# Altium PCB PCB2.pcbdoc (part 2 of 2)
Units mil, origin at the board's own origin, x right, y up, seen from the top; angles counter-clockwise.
Board outline 3822.51 x 2229.86 mil, 2 copper layers (Top Layer, Bottom Layer); 117 components, 92 nets, 474 pads, 260 vias.
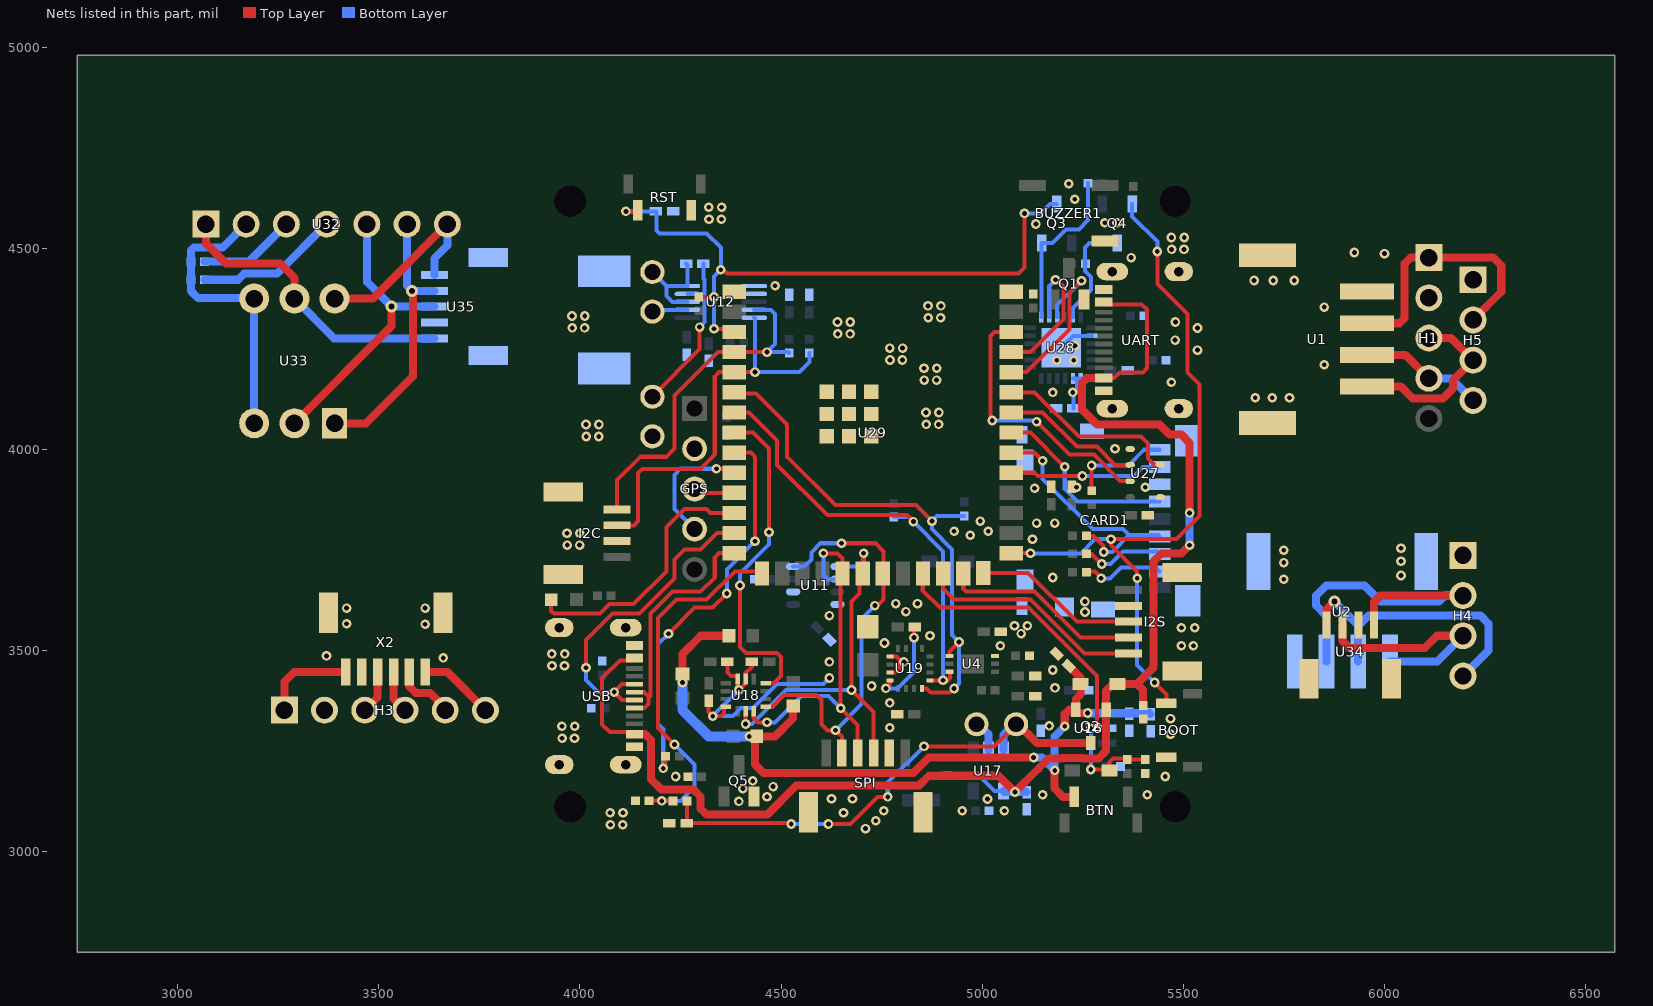
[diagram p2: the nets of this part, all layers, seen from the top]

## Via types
v1: diameter 24.02, hole 12.01, Top Layer to Bottom Layer, 252 vias
v2: diameter 24, hole 12, Top Layer to Bottom Layer, 5 vias
v3: diameter 30, hole 15, Top Layer to Bottom Layer, 3 vias

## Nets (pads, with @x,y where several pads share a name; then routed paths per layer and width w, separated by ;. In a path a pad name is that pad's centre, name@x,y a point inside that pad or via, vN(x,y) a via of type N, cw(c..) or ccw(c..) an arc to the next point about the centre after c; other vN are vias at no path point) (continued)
DATA0: CARD1.7 U29.31 | length 381.6
  Top Layer w10: U29.31@5072.19,3941.69 5130.22,3941.69 5138.34,3933.57 v1(5248.89,3933.57)
  Bottom Layer w10: v1(5248.89,3933.57) 5377.09,3933.57 5400.02,3956.5 5440.75,3956.5 CARD1.7@5440.85,3956.4
DATA1: CARD1.8 R61.2 | length 248.1
  Top Layer w10: R61.2@5271.88,3896.94 v1(5271.88,3959.9)
  Bottom Layer w10: v1(5271.88,3959.9) 5363.42,3959.9 5402.42,3998.9 CARD1.8@5440.85,3998.9
DATA2: CARD1.1 R58.2 | length 211.3
  Top Layer w10: R58.2@5258.92,3689.9 5258.92,3695.4 5260.02,3696.5 5280.02,3696.5 5295.47,3681.05 v1(5295.47,3679.39)
  Bottom Layer w10: v1(5295.47,3679.39) 5317.91,3679.39 5345.02,3706.5 5430.85,3706.5 CARD1.1@5440.85,3696.5
DATA3: CARD1.2 R59.2 | length 208.1
  Top Layer w10: R59.2@5258.92,3739.9 5271.88,3739.9 v1(5296.88,3714.9)
  Bottom Layer w10: v1(5296.88,3714.9) 5318.42,3714.9 5350.02,3746.5 5434.15,3746.5 CARD1.2@5440.85,3739.8
DTR: Q4.3 R62.1 U28.23 | length 283.7
  Bottom Layer w10: U28.23@5225.56,4329.27 5225.02,4329.81 5225.02,4351.5 5270.02,4396.5 5270.02,4428.08 5255.02,4443.08 5255.02,4459.46 R62.1@5257.06,4461.5 5255.02,4463.54 5255.02,4501.5 5266.4,4512.87 Q4.3@5335.02,4512.87
E12S_GAIN: R75.2 U32.4 | length 360.3
  Bottom Layer w20: R75.2@3067.06,4421.5 3150.02,4421.5 3165.02,4436.5 3247.02,4436.5 U32.4@3370.18,4559.66
E12S_SD: R76.2 U32.3 | length 241.7
  Bottom Layer w20: R76.2@3067.06,4466.5 3177.02,4466.5 U32.3@3270.18,4559.66
EI2S_3.3V: U32.1 U33.5 U35.5 | length 744.2
  Top Layer w20: U32.1@3070.18,4559.66 3070.18,4511.34 3120.02,4461.5 3255.02,4461.5 3290.18,4426.34 U33.5@3290.18,4374.66
  Bottom Layer w20: U33.5@3290.18,4374.66 3388.92,4275.91 U35.5@3638.25,4275.91
EI2S_DAT: U32.7 U33.4 U35.1 | length 496.1
  Top Layer w20: U33.4@3390.18,4374.66 3485.18,4374.66 U32.7@3670.18,4559.66
  Bottom Layer w20: U35.1@3638.25,4433.39 3638.25,4474.73 3670.18,4506.66 U32.7@3670.18,4559.66
EI2S_GND: R75.1 R76.1 U32.2 U33.3 U33.6 U35.4 U35.6 U35.7 | length 740.1
  Bottom Layer w20: U32.2@3170.18,4559.66 3112.02,4501.5 3040.02,4501.5 3032.98,4494.46 R76.1@3032.98,4466.5 R75.1@3032.98,4421.5 3032.98,4393.54 3050.02,4376.5 3188.34,4376.5 U33.6@3190.18,4374.66 U33.3@3190.18,4064.66
EI2S_SCK: U32.6 U33.1 U35.2 | length 683.4
  Top Layer w20: U33.1@3390.18,4064.66 3468.18,4064.66 3585.02,4181.5 3585.02,4391.5 v3(3582.5,4394.02)
  Bottom Layer w20: U32.6@3570.18,4559.66 3570.02,4559.5 3570.02,4406.5 v3(3582.5,4394.02) U35.2@3638.25,4394.02
EI2S_WS: U32.5 U33.2 U35.3 | length 727
  Top Layer w20: U33.2@3290.18,4064.66 3531.87,4306.34 v3(3531.87,4354.65)
  Bottom Layer w20: U32.5@3470.18,4559.66 3470.18,4416.34 v3(3531.87,4354.65) U35.3@3638.25,4354.65
ESP_D+: U29.14 USB.6 USB.8 | length 608.7
  Top Layer w10: USB.8@4135.52,3356.97 4160.43,3356.97 4169.96,3366.5 4169.96,3381.44 4175.02,3386.5 ; USB.6@4135.52,3396.34 4158.93,3396.34 4168.77,3386.5 4175.02,3386.5 ; U29.14@4383.21,3741.69 4345.22,3741.69 4335.02,3731.5 4335.02,3681.5 4300.02,3646.5 4230.02,3646.5 4175.02,3591.5 4175.02,3386.5
ESP_D-: U29.13 USB.5 USB.7 | length 805.5
  Top Layer w10: v1(4015.02,3456.79) 4015.02,3526.5 4080.31,3591.79 4147.64,3591.79 4235.02,3679.17 4235.02,3726.5 4260.02,3751.5 4300.02,3751.5 4340.22,3791.69 U29.13@4383.21,3791.69 ; USB.7@4135.52,3376.65 4104.86,3376.65 v1(4085.02,3396.5) 4104.55,3416.02 USB.5@4135.52,3416.02
  Bottom Layer w10: v1(4015.02,3456.79) 4015.02,3426.5 4045.02,3396.5 v1(4085.02,3396.5)
ESP_IO0: BOOT.1 Q4.2 U29.27 | length 1816.7
  Top Layer w10: U29.27@5072.19,3741.69 5119.82,3741.69 v1(5120.02,3741.5) ; v1(5385.02,3679.28) 5385.02,3696.5 5320.02,3761.5 v1(5320.02,3776.5) 5482.54,3776.5 5540.02,3833.98 5540.02,4161.5 5510.02,4191.5 5510.02,4336.5 5435.02,4411.5 v1(5435.02,4491.5) ; v1(5428.31,3420.21) 5457.47,3391.05 BOOT.1@5457.47,3368.5
  Bottom Layer w10: v1(5120.02,3741.5) 5245.02,3741.5 5280.02,3776.5 v1(5320.02,3776.5) ; Q4.2@5372.42,4610.12 5372.42,4579.1 5435.02,4516.5 v1(5435.02,4491.5) ; v1(5385.02,3679.28) 5385.02,3463.5 v1(5428.31,3420.21)
ESP_RST: C48.1 Q3.3 R64.2 RST.1 U29.3 | length 1621.3
  Top Layer w10: v1(4114.01,4591.5) 4140.57,4591.5 RST.1@4143.09,4594.02 ; R64.2@4295.02,4378.54 4332.79,4378.54 v1(4333.01,4378.76) ; v1(4333.01,4299.49) 4375.41,4299.49 U29.3@4383.21,4291.69 ; v1(4350.02,4446.5) 4355.02,4446.5 4365.02,4436.5 5090.02,4436.5 5105.02,4451.5 v1(5105.02,4586.5)
  Bottom Layer w10: v1(4114.01,4591.5) C48.1@4188.56,4591.5 4190.02,4590.04 4190.02,4543.57 4197.09,4536.5 4315.02,4536.5 4350.02,4501.5 v1(4350.02,4446.5) 4333.01,4429.49 v1(4333.01,4378.76) v1(4333.01,4299.49) ; v1(5105.02,4586.5) 5145.02,4586.5 5168.65,4610.12 Q3.3@5185.02,4610.12
ESP_RXD: U28.21 U29.36 | length 437.3
  Top Layer w10: U29.36@5072.19,4191.69 5110.22,4191.69 5216.4,4297.88 5216.4,4390.03 5245.18,4418.81 v2(5246.78,4418.81)
  Bottom Layer w10: U28.21@5186.19,4329.27 5186.19,4358.21 v2(5246.78,4418.81)
ESP_TXD: U28.20 U29.37 | length 370.7
  Top Layer w10: U29.37@5072.19,4241.69 5120.22,4241.69 5202.38,4323.86 5202.38,4404.14 5185.02,4421.5 v2(5182.02,4421.5)
  Bottom Layer w10: U28.20@5166.49,4329.27 5166.49,4405.97 v2(5182.02,4421.5)
ESPI_3.3V: H3.1 X2.6 | length 233.6
  Top Layer w20: H3.1@3265.02,3351.5 3265.02,3421.5 3289.76,3446.24 X2.6@3418.37,3446.24
ESPI_CS: H3.6 X2.1 | length 189
  Top Layer w20: X2.1@3615.22,3446.24 3670.28,3446.24 H3.6@3765.02,3351.5
ESPI_GND: H3.2 X2.5 X2.7 X2.8
  other v1: 3660.02,3481.5 3370.02,3486.5 3615.02,3565.27 3420.02,3566.5 3420.02,3605.27 3615.02,3605.27
ESPI_MISO: H3.5 X2.2 | length 153.2
  Top Layer w20: X2.2@3575.85,3446.24 3575.02,3445.42 3575.02,3411.43 3591.66,3394.79 3627.3,3394.79 3665.02,3357.07 H3.5@3665.02,3351.5
ESPI_MOSI: H3.4 X2.3 | length 106.6
  Top Layer w20: X2.3@3536.48,3446.24 3536.48,3380.04 H3.4@3565.02,3351.5
ESPI_SCLK: H3.3 X2.4 | length 108
  Top Layer w20: H3.3@3465.02,3351.5 3497.11,3383.58 X2.4@3497.11,3446.24
EUART_3.3V: H1.1 H5.2 U1.2 | length 652.4
  Top Layer w20: U1.2@5956.53,4313.37 6036.89,4313.37 6050.02,4326.5 6050.02,4461.5 6065.06,4476.54 H1.1@6109.98,4476.54 ; H1.1@6109.98,4476.54 6270.02,4476.5 6290.02,4456.5 6290.02,4391.58 H5.2@6219.98,4321.54
EUART_GND: H1.2 H5.1 U1.1 U1.5 U1.6
  other v1: 5678.37,4128.33 5720.65,4128.33 5763.62,4128.33 5850.24,4210.27 5850.24,4353.38 5675.77,4419.67 5723.26,4419.67 5775.3,4419.67 6000.02,4486.5 5925.04,4489.34
EUART_RXD: H1.3 H5.3 U1.4 | length 459.5
  Top Layer w20: U1.4@5956.53,4155.89 6040.63,4155.89 6070.02,4126.5 6145.02,4126.5 6170.02,4151.5 6170.02,4171.58 H5.3@6219.98,4221.54 6164.98,4276.54 H1.3@6109.98,4276.54
EUART_TXD: H1.4 H5.4 U1.3 | length 310.3
  Top Layer w20: U1.3@5956.53,4234.63 6051.89,4234.63 H1.4@6109.98,4176.54
  Bottom Layer w20: H1.4@6109.98,4176.54 6164.98,4176.54 H5.4@6219.98,4121.54
GND: BAT+.1 BOOT.2 BUZZER1.3 C1.1 C2.2 C3.1 C4.2 C5.1 C6.1 C7.2 C9.1 C14.1 C15.1 C17.1 C18.1 C19.1 C20.1 C21.1 C22.1 C32.1 C33.1 C36.1 C37.1 C42.1 C43.1 C44.2 C45.2 C46.2 C47.2 C48.2 C49.1 CARD1.6 CARD1.10 CARD1.11 CARD1.12 CARD1.13 CARD1.14 CARD1.15 CARD1.16 CARD1.17 CARD1.18 GPS.2 I2C.3 I2C.5 I2C.6 I2S.4 I2S.6 I2S.7 Q1.2 Q5.2 R1.2 R8.1 R40.1 R42.2 R43.2 R47.2 R48.2 R49.1 R54.1 R55.1 R57.2 R65.2 RST.2 SPI.5 SPI.7 SPI.8 U4.3 U11.1 U11.7 U12.1 U12.2 U12.7 U16.2 U17.2 U18.6 U18.7 U18.11 U19.9 U19.11 U27.1 U27.5 U28.2 U28.25 U29.1 U29.40 U29.41 UART.1 UART.12 UART.13 UART.14 USB.1 USB.12 USB.13 USB.14 VIN+.2 vout+.2 | length 1025.1
  Top Layer w10: C5.1@4320.02,3375.04 4320.02,3346.5 v1(4330.02,3336.5) 4350.02,3336.5 4358.07,3344.55 4358.07,3359.55 U18.11@4362.13,3359.55 ; C6.1@4366.48,3471.5 4366.48,3445.04 4375.02,3436.5 4390.02,3436.5 4392.13,3434.39 U18.7@4392.13,3428.94 4392.13,3404.39 v1(4395.02,3401.5) 4411.82,3418.3 U18.6@4411.82,3428.94 4411.82,3443.6 4427.18,3458.95 C4.2@4427.18,3472.02 ; U19.11@4770.39,3445.41 4783.93,3445.41 4795.02,3456.5 4795.02,3476.5 4786.74,3484.78 U19.9@4770.39,3484.78
  Bottom Layer w10: VIN+.2@4180.02,4342.3 4184.53,4346.81 U12.7@4266.95,4346.81 ; v1(4395.02,3401.5) v1(4330.02,3336.5) 4380.02,3336.5 4400.02,3356.5 4430.02,3356.5 4490.02,3416.5 4605.02,3416.5 v1(4620.02,3431.5) ; U28.25@5196.02,4252.5 5225.55,4282.02 U28.2@5272.8,4282.02
  Bottom Layer w20: BAT+.1@4985.82,3321.5 5014.98,3292.34 U17.2@5014.98,3252.44
  other v1: 4709.63,3057.17 4075.64,3066.87 4106.49,3066.87 4735.02,3076.5 4075.02,3096.5 4107.02,3096.5 4655.02,3096.5 4755.02,3101.5 4950.02,3101.5 5055.02,3101.5 4395.02,3124.89 4625.02,3131.5 4677.43,3131.5 5013.17,3130.67 4465.02,3136.5 5150.02,3141.5 5410.02,3141.5 4405.02,3156.5 4480.02,3161.5 4429.31,3175.81 4237.85,3186.5 5455.02,3186.5 3955.64,3281.87 3986.49,3281.87 5467.75,3291.52 4770.01,3307.78 3955.02,3311.5 3987.02,3311.5 5166.4,3312.47 5467.75,3330.49 4770.01,3369.63 5180.64,3406.87 4725.02,3411.5 5175.02,3451.5 3930.64,3461.87 3961.49,3461.87 4620.02,3471.5 4805.02,3471.5 3930.02,3491.5 3962.02,3491.5 5045.02,3511.5 5495.02,3511.5 5524.83,3511.5 4757.12,3518.49 4870.02,3536.5 5096.49,3541.87 5495.02,3556.5 5528.23,3556.5 5080.02,3561.5 5112.02,3561.5 4620.02,3586.5 4810.02,3596.5 5255.38,3595.65 4785.02,3616.5 4838.97,3616.5 5255.02,3621.5 5175.02,3681.5 3968.24,3761.87 3999.09,3761.87 5125.02,3776.5 4970.02,3786.5 3967.62,3791.5 3999.62,3791.5 4930.02,3796.5 5015.02,3796.5 5135.02,3816.5 5180.02,3816.5 4995.02,3821.5 5130.22,3903.1 5234.36,3905.68 5405.02,3905.71 5330.02,4001.5 4015.64,4031.87 4046.49,4031.87 4015.02,4061.5 4047.02,4061.5 4860.64,4061.87 4891.49,4061.87 4860.02,4091.5 4892.02,4091.5 5175.02,4141.5 5470.02,4166.5 4855.64,4171.87 4886.49,4171.87 4855.02,4201.5 4887.02,4201.5 5185.02,4221.5 5227.41,4221.5 4770.64,4221.87 4801.49,4221.87 5535.02,4246.5 4770.02,4251.5 4802.02,4251.5 5230.71,4257.5 5479.36,4271.5 4640.64,4286.87 4671.49,4286.87 5535.02,4301.5 3980.64,4301.87 4011.49,4301.87 4640.02,4316.5 4672.02,4316.5 5480.02,4316.5 4865.64,4326.87 4896.49,4326.87 3980.02,4331.5 4012.02,4331.5 4865.02,4356.5 4897.02,4356.5 4485.02,4406.5 5370.02,4476.5 5470.64,4496.87 5501.49,4496.87 5470.02,4526.5 5502.02,4526.5 5133.23,4559.9 5304.33,4563.1 5335.02,4563.1 4320.64,4571.87 4351.49,4571.87 4320.02,4601.5 4352.02,4601.5 5230.02,4621.5 5215.02,4659.98
GROVE_3.3V: H4.2 U2.2 U34.4 | length 857.4
  Top Layer w20: U34.4@5974.08,3563.43 5974.08,3620.56 5990.02,3636.5 H4.2@6195.02,3636.5
  Bottom Layer w20: U2.2@5855.65,3472.49 5855.65,3585.87 5830.02,3611.5 5830.02,3636.5 5855.02,3661.5 5950.02,3661.5 5990.02,3621.5 6135.02,3621.5 6150.02,3636.5 H4.2@6195.02,3636.5
GROVE_GND: H4.1 U2.1 U2.5 U2.6 U34.3 U34.5 U34.6
  other v1: 5749.35,3677.12 6040.69,3686.22 5749.35,3718.32 6040.69,3721.78 5749.35,3749.11 6040.69,3753.88
GROVE_SCL: H4.3 U2.4 U34.2 | length 567.4
  Top Layer w20: U34.2@5895.34,3563.43 5895.34,3523.66 5912.5,3506.5 6100.02,3506.5 6130.02,3536.5 H4.3@6195.02,3536.5
  Bottom Layer w20: U2.4@6013.13,3472.49 6131.01,3472.49 H4.3@6195.02,3536.5
GROVE_SDA: H4.4 U2.3 U34.1 | length 738.5
  Top Layer w20: U34.1@5855.97,3563.43 5855.97,3602.45 v3(5875.02,3621.5)
  Bottom Layer w20: v3(5875.02,3621.5) 5934.39,3562.13 5934.39,3560.87 ; U2.3@5934.39,3472.49 5934.39,3560.87 ; H4.4@6195.02,3436.5 6258.21,3499.69 6258.21,3566.5 6238.21,3586.5 5960.02,3586.5 5934.39,3560.87
HEAT: R66.1 U29.9 | length 994.3
  Top Layer w10: v1(4206.98,3206.87) 4212.98,3212.87 R66.1@4212.98,3236.5 ; v1(4220.02,3541.5) 4285.02,3606.5 4330.02,3606.5 v1(4365.02,3641.5) ; U29.9@4383.21,3991.69 4424.82,3991.69 4435.02,3981.5 v1(4435.02,3771.5)
  Bottom Layer w10: v1(4206.98,3206.87) 4206.98,3304.25 4194.04,3317.19 4194.04,3515.51 v1(4220.02,3541.5) ; v1(4365.02,3641.5) 4365.02,3701.5 v1(4435.02,3771.5)
I2S1_DAT: I2S.1 U29.24 | length 564.6
  Top Layer w10: U29.24@4902.7,3691.3 4902.7,3653.82 4930.02,3626.5 5120.02,3626.5 5253.76,3492.76 I2S.1@5363.09,3492.76
I2S1_SCK: I2S.2 U29.25 | length 498.3
  Top Layer w10: U29.25@4952.7,3691.3 4952.7,3653.82 4960.02,3646.5 5130.02,3646.5 5244.39,3532.13 I2S.2@5363.09,3532.13
I2S1_WS: I2S.3 U29.26 | length 410.5
  Top Layer w10: U29.26@5002.7,3692.48 5114.03,3692.48 5235.02,3571.5 I2S.3@5363.09,3571.5
I2S_DAT: U27.7 U29.38 | length 673.8
  Top Layer w10: v1(5024.67,4071.5) 5020.02,4076.15 5020.02,4281.5 5030.22,4291.69 U29.38@5072.19,4291.69 ; v1(5135.02,4068.51) 5217.03,3986.5 5277.8,3986.5 5342.8,3921.5 5366.72,3921.5 U27.7@5367.62,3920.6
  Bottom Layer w10: v1(5024.67,4071.5) 5132.03,4071.5 v1(5135.02,4068.51)
I2S_SCK: U27.6 U29.34 | length 349.5
  Top Layer w10: U29.34@5072.19,4091.69 5072.38,4091.5 5150.02,4091.5 5235.02,4006.5 5285.02,4006.5 5330.02,3961.5 5367.32,3961.5 U27.6@5367.62,3961.2
I2S_WS: U27.3 U29.35 | length 466.7
  Top Layer w10: U29.35@5072.19,4141.69 5129.82,4141.69 5240.02,4031.5 5395.02,4031.5 5411.74,4014.78 5411.74,3977.74 5428.28,3961.2 U27.3@5442.42,3961.2
INT1: U18.4 U29.8 | length 831.9
  Top Layer w10: U29.8@4383.21,4041.69 4429.82,4041.69 4470.02,4001.5 v1(4470.02,3793.82) ; v1(4397.82,3661.5) 4397.82,3508.7 4412.89,3493.63 4490.2,3493.63 4500.02,3483.81 4500.02,3436.5 4482.13,3418.61 U18.4@4461.5,3418.61
  Bottom Layer w10: v1(4397.82,3661.5) 4397.82,3691.78 4470.02,3763.98 v1(4470.02,3793.82)
KEY: D3.2 R56.2 R57.1 U29.23 | length 964.4
  Top Layer w10: U29.23@4852.7,3691.3 4852.02,3690.63 4852.02,3649.5 4895.02,3606.5 5115.02,3606.5 5284.82,3436.69 5284.82,3321.02 v1(5269.67,3305.86) ; v1(5269.85,3203.95) 5313.73,3203.95 D3.2@5316.19,3201.5 5316.19,3222.66 5325.02,3231.5 5357.06,3231.5 R56.2@5360.02,3228.54 R57.1@5405.02,3228.54
  Bottom Layer w10: v1(5269.67,3305.86) 5269.67,3204.12 v1(5269.85,3203.95)
LED: LED1.1 U29.12 | length 661.9
  Top Layer w10: LED1.1@3928.54,3626.37 3928.54,3597.98 3935.02,3591.5 4050.02,3591.5 4073.41,3614.88 4133.41,3614.88 4215.02,3696.5 4215.02,3806.5 4260.02,3851.5 4315.02,3851.5 4324.82,3841.69 U29.12@4383.21,3841.69
MISO: SPI.2 U11.5 U18.1 U29.21 | length 1088.3
  Top Layer w10: U18.1@4461.5,3359.55 4478.07,3359.55 4507.22,3388.7 4588.03,3388.7 4600.02,3376.71 4600.02,3316.5 4615.02,3301.5 v1(4635.02,3301.5) 4650.97,3285.55 SPI.2@4650.97,3245.12 ; v1(4650.02,3766.5) 4735.02,3766.5 4755.02,3746.5 4755.02,3693.63 U29.21@4752.7,3691.3 4755.02,3688.98 4755.02,3626.5 4740.02,3611.5 v1(4733.01,3611.5)
  Bottom Layer w10: U11.5@4529.9,3708.74 4557.26,3708.74 4575.02,3726.5 4575.02,3744.01 4597.5,3766.5 v1(4650.02,3766.5) ; v1(4635.02,3301.5) 4700.02,3366.5 4700.02,3578.51 v1(4733.01,3611.5)
MOSI: SPI.3 U11.3 U18.14 U29.19 | length 928.3
  Top Layer w10: U18.14@4431.5,3349.22 4431.5,3332.49 4442.49,3321.5 v1(4465.02,3321.5) ; v1(4605.02,3741.5) 4640.02,3741.5 4652.7,3728.82 U29.19@4652.7,3691.3 4648.01,3686.62 v1(4648.01,3356.5) 4690.02,3314.49 4690.02,3245.44 SPI.3@4690.34,3245.12
  Bottom Layer w10: v1(4465.02,3321.5) 4485.02,3321.5 4550.55,3387.03 4617.48,3387.03 v1(4648.01,3356.5) ; v1(4605.02,3741.5) 4605.02,3686.5 4615.02,3676.5 4639.39,3676.5 U11.3@4640.14,3677.25
RTS: Q3.2 R63.1 U28.19 | length 414.8
  Bottom Layer w10: U28.19@5146.81,4329.27 5146.81,4512.07 Q3.2@5147.62,4512.87 5174.01,4512.87 5207.64,4546.5 5240.02,4546.5 5262.98,4569.46 R63.1@5262.98,4661.5
RXD: GPS.3 U29.11 | length 102.2
  Top Layer w10: GPS.3@4285.02,3901.5 4294.82,3891.69 U29.11@4383.21,3891.69
SCL: R72.1 U4.6 U19.1 U29.7 | length 1140
  Top Layer w10: U29.7@4383.21,4091.69 4419.82,4091.69 4490.02,4021.5 4490.02,3961.5 4615.02,3836.5 4812.5,3836.5 v1(4828.76,3820.24) ; U19.1@4869.84,3425.73 v1(4902.49,3425.73) 4914.25,3425.73 4920.02,3431.5 4920.02,3445.61 U4.6@4918.82,3446.81
  Bottom Layer w10: R72.1@4780.02,3831.46 4817.54,3831.46 v1(4828.76,3820.24) 4902.49,3746.51 v1(4902.49,3425.73)
SCL1: I2C.2 R74.2 U12.5 U29.5 | length 989.6
  Top Layer w10: I2C.2@4091.95,3811.18 4134.7,3811.18 4144.7,3821.18 4144.7,3941.18 4155.02,3951.5 4300.02,3951.5 4335.02,3986.5 4335.02,4181.5 4345.22,4191.69 U29.5@4383.21,4191.69 4434.92,4191.69 v1(4435.02,4191.8)
  Bottom Layer w10: U12.5@4433.09,4327.13 4435.02,4325.2 v1(4435.02,4191.8) 4545.32,4191.8 4570.02,4216.5 R74.2@4570.02,4239.46
SCLK: SPI.4 U11.4 U18.13 U29.20 | length 955
  Top Layer w10: v1(4411.82,3317) U18.13@4411.82,3349.22 ; v1(4705.02,3741.5) 4705.02,3693.63 U29.20@4702.7,3691.3 4695.02,3683.63 4695.02,3641.5 4675.02,3621.5 v1(4675.02,3401.5) 4729.71,3346.81 SPI.4@4729.71,3245.12
  Bottom Layer w10: v1(4411.82,3317) 4428,3317 4512.5,3401.5 v1(4675.02,3401.5) ; U11.4@4640.14,3708.74 4697.26,3708.74 4705.02,3716.5 v1(4705.02,3741.5)
SD_CMD: CARD1.3 R60.2 U29.32 | length 630
  Top Layer w10: U29.32@5072.19,3991.69 5129.82,3991.69 v1(5150.02,3971.5) ; R60.2@5258.92,3784.9 5276.62,3784.9 5301.88,3759.64 v1(5301.88,3744.9)
  Bottom Layer w10: v1(5150.02,3971.5) 5150.02,3926.5 5275.02,3801.5 5350.02,3801.5 5365.02,3786.5 ; v1(5301.88,3744.9) 5323.42,3744.9 5365.02,3786.5 ; CARD1.3@5440.85,3783.1 5437.45,3786.5 5365.02,3786.5
SD_SCLK: CARD1.5 U29.33 | length 472.1
  Top Layer w10: U29.33@5072.19,4041.69 5119.82,4041.69 v1(5205.02,3956.56)
  Bottom Layer w10: v1(5205.02,3956.56) 5205.02,3901.5 5236.72,3869.8 CARD1.5@5440.85,3869.8
SDA: R71.1 U4.4 U19.16 U29.6 | length 1339.1
  Top Layer w10: U29.6@4383.21,4141.69 4386.33,4138.57 4437.95,4138.57 4515.02,4061.5 4515.02,3981.5 4635.02,3861.5 4835.02,3861.5 v1(4875.02,3821.5) ; U19.16@4849.65,3405.53 4860.99,3405.53 4871.31,3395.21 4919.7,3395.21 v1(4930.02,3405.53) ; U4.4@4918.82,3486.18 4918.82,3497.48 v1(4942.33,3520.99)
  Bottom Layer w10: v1(4930.02,3405.53) 4942.33,3417.83 v1(4942.33,3520.99) 4925.02,3538.3 4925.02,3751.5 4875.02,3801.5 v1(4875.02,3821.5) 4887.98,3834.46 R71.1@4955.02,3834.46
SDA1: I2C.1 R73.2 U12.4 U29.4 | length 870.8
  Top Layer w10: I2C.1@4091.95,3850.55 4091.95,3923.43 4150.02,3981.5 4215.02,3981.5 4235.02,4001.5 4235.02,4133.96 4342.75,4241.69 U29.4@4383.21,4241.69 4464.82,4241.69 v1(4465.02,4241.5)
  Bottom Layer w10: U12.4@4433.09,4346.81 4474.71,4346.81 4485.02,4336.5 4485.02,4261.5 v1(4465.02,4241.5) 4517.98,4241.5 R73.2@4520.02,4239.46
SETC: C8.2 U19.12 | length 223.3
  Top Layer w10: v1(4760.45,3405.79) 4770.39,3415.73 U19.12@4770.39,3425.72 ; v1(4830.45,3531.83) 4830.45,3556.45 C8.2@4832.35,3558.36
  Bottom Layer w10: v1(4760.45,3405.79) 4789.31,3405.79 4830.45,3446.93 v1(4830.45,3531.83)
TXD: GPS.4 U29.10 | length 314.3
  Top Layer w10: v1(4339.02,3951.66) 4373.17,3951.66 U29.10@4383.21,3941.69
  Bottom Layer w10: GPS.4@4285.02,3801.5 4235.02,3851.5 4235.02,3936.5 4250.18,3951.66 v1(4339.02,3951.66)
V_OUT: BTN.2 C1.2 C32.2 C33.2 D2.1 Q2.2 R67.2 R68.2 R69.2 R70.2 U16.1 | length 2067.2
  Top Layer w20: R68.2@4255.02,3441.16 4255.02,3491.5 4300.02,3536.5 R70.2@4370.36,3536.5 ; R67.2@4435.02,3276.16 4435.02,3216.5 4456.02,3195.5 4828.58,3195.48 4866.94,3233.84 v1(5127.72,3233.84) ; R67.2@4439.68,3286.5 4485.02,3286.5 4530.02,3331.5 R69.2@4530.02,3361.84 ; v1(5180.02,3201.97) 5180.02,3156.5 5200.68,3135.84 BTN.2@5228.01,3135.84 ; v1(5205.02,3311.5) 5205.02,3341.5 5216.56,3353.04 Q2.2@5232.42,3353.04 ; C1.2@5215.19,3461.32 5243.85,3432.66 D2.1@5243.85,3416.5 5243.85,3390.33 5232.42,3378.9 Q2.2@5232.42,3353.04 ; v1(5261.83,3344.69) 5240.77,3344.69 Q2.2@5232.42,3353.04
  Top Layer w25: v1(4255.02,3420.53) R68.2@4255.02,3441.16 ; v1(4420.89,3286.5) R67.2@4439.68,3286.5
  Bottom Layer w20: v1(5127.72,3233.84) 5148.15,3233.84 v1(5180.02,3201.97) 5180.02,3286.5 v1(5205.02,3311.5) ; v1(5261.83,3344.69) 5262.62,3343.9 U16.1@5310.44,3343.9 5416.16,3343.9 C32.2@5418.56,3341.5
  Bottom Layer w25: v1(4255.02,3420.53) 4255.02,3351.5 4320.02,3286.5 v1(4420.89,3286.5)
VBAT: BAT+.2 C2.1 Q2.3 R53.2 U17.3 | length 1288
  Top Layer w10: R53.2@4265.68,3125.81 4265.68,3071.39 C2.1@4265.1,3070.81 4522.85,3070.81 v1(4525.02,3068.64) ; v1(4617.5,3068.64) 4672.16,3068.64 4739.59,3136.07 v1(4765.02,3136.07) ; v1(4855.02,3261.5) 5029.22,3261.5 BAT+.2@5084.22,3316.5
  Top Layer w20: BAT+.2@5084.22,3321.5 5135.76,3269.96 Q2.3@5270.02,3269.96
  Bottom Layer w10: v1(4525.02,3068.64) v1(4617.5,3068.64) ; v1(4765.02,3136.07) 4765.02,3171.5 v1(4855.02,3261.5)
  Bottom Layer w20: U17.3@5052.46,3252.44 5052.46,3289.74 BAT+.2@5084.22,3321.5
VBAT_AD: R53.1 R54.2 U29.15 | length 922.5
  Top Layer w10: R54.2@4172.06,3126.5 v1@4202.69,3126.5 ; v1(4203.06,3126.13) v1@4202.69,3126.5 ; R53.1@4231.6,3125.81 4230.91,3126.5 v1@4202.69,3126.5 ; v1(4235.02,3266.21) 4235.02,3266.44 4194.04,3307.5 4194.04,3580.51 4240.02,3626.5 4315.02,3626.5 4385.02,3696.5 4447.5,3696.5 U29.15@4452.7,3691.3
  Bottom Layer w10: v1(4203.06,3126.13) 4249.65,3126.13 4285.02,3161.5 4285.02,3216.21 v1(4235.02,3266.21)
VIN: C3.2 C49.2 D2.2 Q2.1 R2.1 R49.2 U17.4 U28.7 U28.8 UART.2 UART.11 USB.2 USB.11 | length 3851.7
  Top Layer w10: USB.11@4135.52,3292 4130.05,3297.48 4074.04,3297.48 4055.02,3316.5 4055.02,3431.53 4099,3475.51 4130.05,3475.51 USB.2@4135.52,3480.98 ; v1(5225.02,4141.5) 5247.42,4141.5 5247.81,4141.11 ; UART.2@5301.52,4177.01 5327.91,4177.01 5342.4,4191.5 5399.56,4191.5 5409.56,4201.5 5409.56,4346.96 5396,4360.52 5306.99,4360.52 UART.11@5301.52,4365.99
  Top Layer w20: USB.11@4135.52,3292 4161.93,3292 4176.07,3277.86 4176.07,3180.45 4202.4,3154.12 4282.4,3154.12 4300.02,3136.5 4300.02,3106.5 4314.16,3092.36 4465.94,3092.36 4537.65,3164.06 4778,3164.06 4778.43,3164.49 4801.61,3164.49 4802.04,3164.06 4842.58,3164.06 4867.06,3188.54 5040.66,3188.54 v1(5081.24,3147.96) 5139.13,3205.84 5139.31,3205.84 5155.71,3222.24 5155.71,3222.43 5165.23,3231.94 5197.25,3231.94 5197.55,3232.25 5250.16,3232.25 5250.46,3231.94 5289.58,3231.94 5307.62,3249.99 Q2.1@5307.62,3353.04 5307.62,3399.1 5325.02,3416.5 D2.2@5336.19,3416.5 5385.02,3416.5 ; UART.2@5301.52,4177.01 5260.53,4177.01 5247.81,4164.29 5247.81,4141.11 5247.81,4098.7 5285.02,4061.5 5440.61,4061.5 5465.61,4036.5 5495.02,4036.5 5515.44,4016.08 v1(5515.44,3841.92) ; R49.2@5400.02,3363.54 5400.02,3401.5 5385.02,3416.5 ; v1(5515.44,3761.5) 5495.44,3741.5 5445.93,3741.5 5425.93,3721.5 5425.93,3457.41 5385.02,3416.5
  Bottom Layer w10: R2.1@4914.06,3188.5 4993.02,3188.5 5030.97,3150.55 U17.4@5052.46,3150.55 ; U28.8@5225.56,4175.72 5235.29,4175.72 ; C49.2@5226.48,4101.5 5226.48,4140.04 v1(5225.02,4141.5) 5235.29,4151.77 5235.29,4175.72 ; U28.7@5245.23,4175.72 5235.29,4175.72
  Bottom Layer w20: U17.4@5052.46,3150.55 5055.05,3147.96 v1(5081.24,3147.96) C3.2@5110.02,3147.96 ; v1(5515.44,3761.5) v1(5515.44,3841.92)
VIN+: C16.2 R7.2 U12.8 U12.10 VIN+.1 | length 241
  Bottom Layer w10: VIN+.1@4180.02,4440.7 4214.85,4405.87 ; C16.2@4263.56,4461.5 4266.95,4458.11 U12.10@4266.95,4405.87 4214.85,4405.87 ; U12.8@4266.95,4366.5 4230.02,4366.5 4215.02,4381.5 4215.02,4405.7 4214.85,4405.87
VOUT+: C16.1 R7.1 U12.9 vout+.1 | length 430.2
  Top Layer w10: vout+.1@4180.02,4130.7 4180.02,4131.5 4297.48,4248.96 v1(4297.48,4303.62)
  Bottom Layer w10: U12.9@4266.95,4386.18 4267.27,4386.5 4307.95,4386.5 4310.02,4388.57 ; v1(4297.48,4303.62) 4310.02,4316.16 4310.02,4388.57 ; C16.1@4306.48,4461.5 4306.48,4425.04 4310.02,4421.5 4310.02,4388.57
pads on no net: BOOT.3 BOOT.4 BTN.3 BTN.4 CARD1.9 GPS.5 H1.5 RST.3 RST.4 SCREW1.1 SCREW2.1 SCREW3.1 SCREW4.1 U4.7 U16.4 U18.2 U18.3 U18.9 U18.10 U19.3 U19.5 U19.6 U19.7 U19.14 U19.15 U27.2 U28.1 U28.3 U28.9 U28.10 U28.11 U28.12 U28.13 U28.14 U28.15 U28.16 U28.17 U28.18 U28.22 U28.24 U29.28 U29.29 U29.30 UART.3 UART.6 UART.8 UART.9 USB.3 USB.9
copper on no net: | length 252.1
  Top Layer w10: 5301.52,4261.65 5342.37,4261.65 v2(5344.52,4259.5) ; 5301.52,4301.02 5379.49,4301.02 v2(5381.02,4299.5)
  Bottom Layer w10: 5272.8,4262.34 5341.68,4262.34 v2(5344.52,4259.5) 5381.02,4296 v2(5381.02,4299.5)
  other v1: 3870.02,3333.07 3854.16,3352.56 5600.89,3582.84 5585.02,3602.68 5595.89,4275.32 5580.02,4294.81 3870.02,4348.19 3854.16,4367.68

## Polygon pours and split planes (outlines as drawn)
VIN+ on Bottom Layer (solid, remove dead copper, pour order 8): 3985.02,4381.5 4215.02,4381.5 4215.02,4487.99 3985.02,4487.99
GND on Top Layer (solid, remove dead copper): 3890.02,3026.5 5565.02,3026.5 5565.02,4701.5 3890.02,4701.5
VOUT+ on Bottom Layer (solid, remove dead copper, pour order 10): 3992.26,4096.5 4215.02,4096.5 4215.02,4241.5 3992.26,4241.5
ESPI_GND on Top Layer (solid, remove dead copper, pour order 2): 3335.02,3411.5 3685.02,3411.5 3685.02,3646.5 3335.02,3646.5
GND on Bottom Layer (solid, remove dead copper, pour order 12): 3890.02,3026.5 5565.02,3026.5 5565.02,4701.5 3890.02,4701.5
ESPI_GND on Bottom Layer (solid, remove dead copper, pour order 14): 3335.02,3411.5 3685.02,3411.5 3685.02,3646.5 3335.02,3646.5
ESPI_GND on Bottom Layer (solid, remove dead copper, pour order 16): 3310.02,3291.5 3415.02,3291.5 3415.02,3496.5 3310.02,3496.5
EI2S_GND on Bottom Layer (solid, remove dead copper, pour order 22): 3011.91,4156.5 3750.02,4156.5 3750.02,4609.66 3011.91,4609.66
EUART_GND on Top Layer (solid, remove dead copper, pour order 4): 5622.45,4501.5 5665.02,4544.07 6277.51,4544.07 6277.51,4544 6322.51,4499 6322.51,4049 6277.51,4004 5665.02,4004 5622.52,4046.5 5622.52,4049 5622.45,4049.07
GROVE_GND on Top Layer (solid, remove dead copper, pour order 6): 5665.02,3806.5 5620.02,3761.5 5620.02,3411.5 5665.02,3366.5 6235.02,3366.5 6280.02,3411.5 6280.02,3761.5 6235.02,3806.5
EUART_GND on Bottom Layer (solid, remove dead copper, pour order 18): 5622.45,4501.5 5665.02,4544.07 6277.51,4544.07 6277.51,4544 6322.51,4499 6322.51,4049 6277.51,4004 5665.02,4004 5622.52,4046.5 5622.52,4049 5622.45,4049.07
GROVE_GND on Bottom Layer (solid, remove dead copper, pour order 20): 5665.02,3806.5 5620.02,3761.5 5620.02,3411.5 5665.02,3366.5 6235.02,3366.5 6280.02,3411.5 6280.02,3761.5 6235.02,3806.5

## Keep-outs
Board Outline Layer:
  lines w10: 3244.31,3242.16 cw(c3246.14,3288.99) 3199.31,3287.16 3199.31,3406.5 cw(c3389.15,3405.26) 3220.02,3491.5 cw(c3669.07,3301.75) 3310.02,3631.5 cw(c3359.97,3594.59) 3355.02,3656.5 3676.84,3656.5 cw(c3671.89,3594.59) 3721.84,3631.5 cw(c3362.79,3301.75) 3811.84,3491.5 cw(c3642.71,3405.26) 3832.56,3406.5 3832.56,3376.38 ; 3246.14,3242.12 3785.72,3242.12 ; 3732.73,4619.68 3029.96,4619.68 ccw(c3028.78,4590.85) 3000.18,4594.66 3000.02,4226.5 ccw(c3298.44,4223.04) 3560.18,4079.66 cw(c3612.69,4039.22) 3623.19,4104.66 3760.18,4104.66 ccw(c3734.62,4201.94) 3835.18,4199.66 ; 3735.01,4619.66 cw(c3712.84,4499.22) 3835.18,4504.66 3835.18,4391.66 3835.02,4391.5 3895.02,4391.5 ; 3787.56,3242.16 ccw(c3785.72,3288.99) 3832.56,3287.16 ; 3832.59,3288.99 3832.59,3309.25 ; 3833.44,3376.38 3893.44,3376.38 ; 3833.74,3309.25 3893.59,3309.25 ; 3835.32,4199.66 3835.32,4324.37 3895.17,4324.37 3895.17,3376.38 ; 3895.37,3309.25 3895.37,3076.85 ccw(c3946.2,3082.68) 3940.37,3031.85 5515.17,3031.85 ccw(c5509.34,3082.68) 5560.17,3076.85 5560.17,3559.02 5620.17,3559.02 5620.17,3411.5 ; 3895.37,4391.5 3895.37,4651.65 cw(c3946.2,4645.82) 3940.37,4696.65 4371.15,4696.65 4371.3,4696.5 4380.02,4696.5 4380.02,4456.5 5065.02,4456.5 5075.03,4456.5 5075.03,4696.65 ; 5075.02,4696.5 5075.17,4696.65 5515.17,4696.65 cw(c5509.34,4645.82) 5560.17,4651.65 ; 5559.72,4651.65 5559.72,4318.63 5619.72,4318.63 5622.52,4321.43 5622.52,4499 cw(c5665.02,4501.5) 5667.52,4544 6277.51,4544 cw(c6271.68,4493.17) 6322.51,4499 6322.51,4049 cw(c6271.68,4054.83) 6277.51,4004 5667.52,4003.99 cw(c5665.02,4046.5) 5622.52,4049 5622.52,4251.5 5619.87,4251.5 5560.02,4251.5 5560.02,4061.97 ; 5560.17,4061.97 5560.17,3626.5 5620.02,3626.5 5620.02,3761.5 cw(c5670.85,3755.67) 5665.02,3806.5 5690.02,3806.5 6225.02,3806.5 ; 5620.02,3411.5 ccw(c5670.85,3417.33) 5665.02,3366.5 6235.02,3366.5 ccw(c6229.19,3417.33) 6280.02,3411.5 6280.02,3761.5 ccw(c6229.19,3755.67) 6235.02,3806.5 6215.02,3806.5
Multi-Layer:
  region: 4365.02,3568.87 4310.07,3568.87 4225.02,3486.31 4225.02,3431.5 4205.12,3431.5 4205.12,3501.11 4300.16,3591.5 4365.02,3591.5
  region: 4224.93,3401.5 4224.93,3341.84 4305.21,3256.5 4370.02,3256.5 4370.02,3231.6 4295.16,3231.6 4205.02,3326.38 4205.02,3401.5
  region: 4455.12,3256.41 4487.39,3256.41 4560.02,3331.5 4560.02,3376.05 4585.15,3376.05 4585.15,3321.59 4499.51,3231.5 4455.12,3231.5
  region: 4560.23,3431.13 4560.23,3491.05 4480.39,3566.4 4420.47,3566.4 4420.47,3591.52 4490.47,3591.52 4585.02,3501.46 4585.02,3431.13
  region: 4310.07,3568.87 4477.65,3568.87 4560.23,3491.05 4560.02,3331.5 4487.39,3256.41 4305.21,3256.99 4224.93,3341.84 4225.02,3486.31

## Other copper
Top Layer:
  drawing of 284 lines, arcs and shapes, not listed
Bottom Layer:
  drawing of 231 lines, arcs and shapes, not listed

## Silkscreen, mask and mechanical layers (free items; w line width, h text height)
Top Silkscreen Layer:
  text "3.3V" at 3030.5,4462.35 h39.37
  text "GND" at 3130.5,4462.35 h39.37
  text "SD" at 3245.02,4461.5 h39.37
  text "GAIN" at 3325.02,4461.5 h39.37
  text "WS" at 3445.02,4461.5 h39.37
  text "SCK" at 3535.02,4461.5 h39.37
  text "DAT" at 3635.02,4461.5 h39.37
  text "GND" at 6315.02,4386.5 h39.37 r90
  text "3.3V" at 6317.29,4281.86 h39.37 r90
  text "RXD" at 6315.02,4186.5 h39.37 r90
  text "TXD" at 6315.02,4086.5 h39.37 r90
  text "GND" at 6095.02,3771.5 h39.37 r270
  text "3.3V" at 6095.02,3676.5 h39.37 r270
  text "SCL /  RXD" at 6055.02,3571.5 h39.37 r270
  text "SDA /  TXD" at 6055.02,3471.5 h39.37 r270
  text "3.3V" at 3225.02,3251.5 h39.37
  text "GND" at 3330.02,3251.5 h39.37
  text "CLK" at 3430.02,3251.5 h39.37
  text "MOSI" at 3525.02,3251.5 h39.37
  text "MISO" at 3630.02,3251.5 h39.37
  text "CS" at 3740.02,3251.5 h39.37
Bottom Silkscreen Layer:
  text "3.3V" at 6055.02,4526.5 h39.37 r90
  text "GND" at 6315.02,4456.5 h39.37 r90
  text "GND" at 6055.02,4411.5 h39.37 r90
  text "3.3V" at 6315.02,4361.5 h39.37 r90
  text "RXD" at 6055.02,4311.5 h39.37 r90
  text "RXD" at 6315.02,4256.5 h39.37 r90
  text "TXD" at 6054.31,4210.65 h39.37 r90
  text "TXD" at 6315.02,4156.5 h39.37 r90
  text "3.3V" at 3305.02,3251.5 h39.37
  text "GND" at 3400.02,3251.5 h39.37
  text "CLK" at 3500.02,3251.5 h39.37
  text "MOSI" at 3610.02,3251.5 h39.37
  text "MISO" at 3715.02,3251.5 h39.37
  text "CS" at 3790.02,3251.5 h39.37
Mechanical Layer:
  lines w1: 4205.02,3326.38 4295.16,3231.6 4370.02,3231.6 4370.02,3256.5 4305.21,3256.5 4224.93,3341.84 4224.93,3401.5 4205.02,3401.5 4205.02,3326.38 ; 4205.12,3431.5 4225.02,3431.5 4225.02,3486.31 4310.07,3568.87 4365.02,3568.87 4365.02,3591.5 4300.16,3591.5 4205.12,3501.11 4205.12,3431.5 ; 4420.47,3566.4 4480.39,3566.4 4560.23,3491.05 4560.23,3431.13 4585.02,3431.13 4585.02,3501.46 4490.47,3591.52 4420.47,3591.52 4420.47,3566.4 ; 4455.12,3231.5 4499.51,3231.5 4585.15,3321.59 4585.15,3376.05 4560.02,3376.05 4560.02,3331.5 4487.39,3256.41 4455.12,3256.41 4455.12,3231.5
